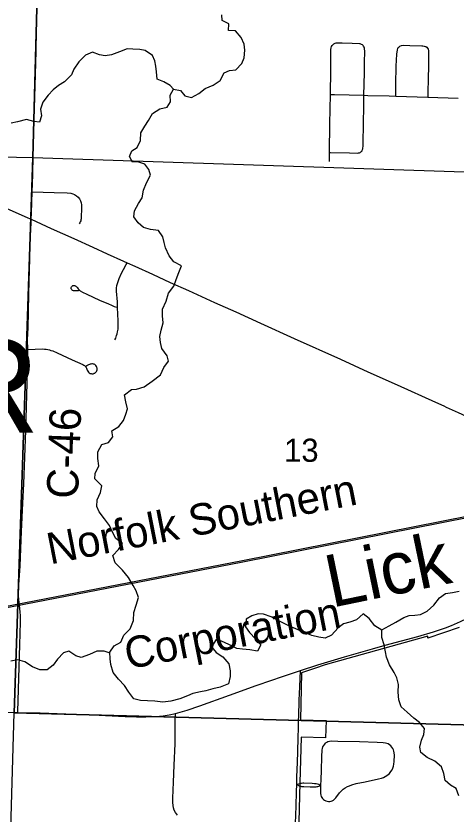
# Model space of a CAD drawing. Extents: x 0 to 34, y 0 to 22.
# Drawn here: x 5.686 to 6.482, y 19.283 to 20.728 of the extents above; entities that cross this region are included whole.
import ezdxf

# ---------------------------------------------------------------- set-up
doc = ezdxf.new("R2010")
doc.units = 0
for name, color, linetype in [('GM_X_City_Street', 7, 'Continuous'), ('GM_X_County_Road', 7, 'Continuous'), ('GM_X_County_Road_Text', 7, 'Continuous'), ('GM_X_Minor_River', 7, 'Continuous'), ('GM_X_Minor_River_Text', 7, 'Continuous'), ('GM_X_Rail_Line', 7, 'Continuous'), ('GM_X_Rail_Line_Text', 7, 'Continuous'), ('GM_X_Section', 7, 'Continuous'), ('GM_X_Section_Text', 7, 'Continuous'), ('GM_X_State_Route', 7, 'Continuous'), ('GM_X_Township_Road', 7, 'Continuous'), ('GM_X_Township_Text', 7, 'Continuous'), ('GM_X_US_Route', 7, 'Continuous')]:
    doc.layers.add(name, color=color, linetype=linetype)

msp = doc.modelspace()

# ---------------------------------------------------------------- linework, layer by layer
at = {"layer": 'GM_X_City_Street'}
for points in [[(6.2371, 19.3357), (6.237, 19.3207), (6.2374, 19.3177), (6.2381, 19.3155), (6.2392, 19.3135), (6.2406, 19.3116), (6.2422, 19.3099), (6.2441, 19.3085), (6.2467, 19.3073), (6.249, 19.3065), (6.2513, 19.3062), (6.2536, 19.3063), (6.2559, 19.3067), (6.2581, 19.3075), (6.2601, 19.3087), (6.2619, 19.3101), (6.2643, 19.3128), (6.2714, 19.3216), (6.2748, 19.3253), (6.2781, 19.3282), (6.2817, 19.3309), (6.2855, 19.3332), (6.289, 19.3348), (6.2937, 19.3364), (6.3016, 19.3385), (6.3174, 19.3419), (6.3417, 19.3473), (6.3471, 19.3485), (6.3506, 19.3497), (6.3539, 19.3512), (6.357, 19.353), (6.3593, 19.3549), (6.3615, 19.357), (6.3642, 19.3603), (6.3661, 19.3633), (6.3677, 19.3666), (6.3688, 19.37), (6.3695, 19.3736), (6.3699, 19.3784), (6.3703, 19.3902), (6.3701, 19.3945), (6.3696, 19.3974), (6.3688, 19.3996), (6.3675, 19.4022), (6.3658, 19.4047), (6.3637, 19.4069), (6.3614, 19.4088), (6.3589, 19.4104), (6.3567, 19.4113), (6.3545, 19.412), (6.3503, 19.4125), (6.3392, 19.413), (6.3075, 19.4139), (6.2683, 19.415), (6.2559, 19.4152), (6.2529, 19.4149), (6.2501, 19.4142), (6.248, 19.4132), (6.2455, 19.4116), (6.2438, 19.41), (6.242, 19.4077), (6.2406, 19.4051), (6.2397, 19.4023), (6.2392, 19.3994), (6.2387, 19.387), (6.2379, 19.3628), (6.2374, 19.3453), (6.2371, 19.3357)], [(6.1938, 19.337), (6.1948, 19.3373), (6.1976, 19.3383), (6.2008, 19.3393), (6.2028, 19.3396), (6.2048, 19.3397), (6.2065, 19.3397), (6.2218, 19.3392), (6.2257, 19.3389), (6.2291, 19.3385), (6.2317, 19.3381), (6.2337, 19.3375), (6.2356, 19.3366), (6.2371, 19.3357)], [(6.1938, 19.337), (6.1981, 19.3346), (6.201, 19.3337), (6.2026, 19.3333), (6.2046, 19.3332), (6.2065, 19.3331), (6.2184, 19.3327), (6.2213, 19.3326), (6.2242, 19.3326), (6.2267, 19.3326), (6.2291, 19.3328), (6.231, 19.3331), (6.2322, 19.3334), (6.2337, 19.334), (6.2352, 19.3347), (6.2371, 19.3357)]]:
    msp.add_lwpolyline(points, dxfattribs=at)
at = {"layer": 'GM_X_County_Road'}
for points in [[(5.7158, 20.4096), (5.7167, 20.44), (5.7175, 20.476), (5.719, 20.5313), (5.7198, 20.5604), (5.7218, 20.6219), (5.7228, 20.6641), (5.7237, 20.702), (5.7249, 20.7536), (5.7265, 20.8192)], [(6.2547, 20.5859), (6.2554, 20.6296), (6.2558, 20.6668), (6.2563, 20.6703), (6.2569, 20.6726), (6.258, 20.6744), (6.259, 20.6757)], [(6.3154, 20.5843), (6.3161, 20.6251), (6.3164, 20.6438), (6.3168, 20.6642), (6.3165, 20.6684), (6.3162, 20.67), (6.3157, 20.6715), (6.3148, 20.6732), (6.314, 20.6742), (6.3125, 20.6754), (6.3112, 20.6763), (6.31, 20.6767), (6.3088, 20.6771), (6.3072, 20.6774), (6.2939, 20.6779), (6.2758, 20.6785), (6.2643, 20.6784), (6.263, 20.6781), (6.2615, 20.6775), (6.2602, 20.6767), (6.259, 20.6757)], [(6.3729, 20.5825), (6.373, 20.5869), (6.3731, 20.6046), (6.3739, 20.6369), (6.375, 20.6586), (6.3758, 20.6667), (6.3765, 20.6687), (6.3775, 20.6705), (6.3788, 20.672), (6.3805, 20.6732), (6.383, 20.6743), (6.3863, 20.6748), (6.3981, 20.6746), (6.4199, 20.6739), (6.4221, 20.6737), (6.4243, 20.6733), (6.4262, 20.6727), (6.4275, 20.6722), (6.4289, 20.6711), (6.4304, 20.6696), (6.4313, 20.6677), (6.432, 20.6651), (6.4321, 20.6623), (6.4322, 20.6594), (6.432, 20.6463), (6.4318, 20.637), (6.4315, 20.6146), (6.431, 20.5891), (6.431, 20.586), (6.4309, 20.5807)], [(6.2532, 20.4806), (6.2533, 20.4967), (6.2536, 20.5171), (6.2538, 20.5326), (6.2547, 20.5859)], [(6.2532, 20.4806), (6.2548, 20.4806), (6.2893, 20.4799), (6.3035, 20.4796), (6.3055, 20.4798), (6.3071, 20.4803), (6.3085, 20.4808), (6.3096, 20.4816), (6.3108, 20.4826), (6.3119, 20.4838), (6.3124, 20.4848), (6.3129, 20.4858), (6.3133, 20.4873), (6.3136, 20.489), (6.3138, 20.4913), (6.314, 20.4966), (6.314, 20.5046), (6.3145, 20.5251), (6.3152, 20.5723), (6.3154, 20.5843)], [(6.2547, 20.5859), (6.2562, 20.5859), (6.262, 20.5859), (6.3154, 20.5843)], [(6.3154, 20.5843), (6.3222, 20.5841), (6.3608, 20.583), (6.3729, 20.5825)], [(6.3729, 20.5825), (6.3924, 20.5819), (6.4309, 20.5807), (6.4858, 20.579)], [(6.253, 20.4645), (6.2531, 20.4706), (6.2531, 20.4743), (6.2532, 20.4806)], [(5.714, 20.3598), (5.7146, 20.3712), (5.7158, 20.4096)], [(5.7077, 20.1243), (5.7075, 20.1416), (5.7083, 20.1639), (5.7089, 20.1925), (5.7097, 20.2254), (5.711, 20.2683), (5.7114, 20.2875), (5.7121, 20.3167), (5.7136, 20.3539), (5.714, 20.3598)], [(5.6896, 19.4674), (5.6896, 19.4693), (5.6902, 19.4892), (5.6914, 19.5295), (5.6934, 19.5897), (5.6946, 19.6307), (5.6945, 19.642), (5.6939, 19.6496), (5.6927, 19.6606), (5.6921, 19.6652), (5.6914, 19.6731), (5.6909, 19.6777), (5.6919, 19.6982), (5.6938, 19.7329), (5.6967, 19.7949), (5.6991, 19.8463), (5.7008, 19.8811), (5.7041, 19.9774), (5.707, 20.0848), (5.7077, 20.1243)], [(5.7077, 20.1243), (5.7344, 20.1252), (5.738, 20.1249), (5.7413, 20.1245), (5.7438, 20.1242), (5.747, 20.1235), (5.7497, 20.1226), (5.7529, 20.1215), (5.7609, 20.118), (5.7881, 20.1055), (5.8074, 20.0968), (5.8088, 20.096), (5.8102, 20.0952), (5.8111, 20.0945), (5.8122, 20.0934), (5.8133, 20.0917), (5.8139, 20.0903), (5.8146, 20.0885), (5.8154, 20.0867), (5.8163, 20.0848), (5.8176, 20.083), (5.8188, 20.0819), (5.8208, 20.0809), (5.8222, 20.0806), (5.8236, 20.0803), (5.8246, 20.0803), (5.8258, 20.0804), (5.827, 20.0807), (5.828, 20.0811), (5.8289, 20.0816), (5.8302, 20.0826), (5.831, 20.0833), (5.8318, 20.0844), (5.8324, 20.0857), (5.8329, 20.0874), (5.8331, 20.0888), (5.833, 20.0901), (5.8328, 20.0915), (5.832, 20.0936), (5.8308, 20.0954), (5.83, 20.0961), (5.829, 20.0968), (5.8276, 20.0974), (5.8264, 20.0978), (5.8249, 20.098), (5.8236, 20.098), (5.822, 20.0979), (5.8207, 20.0976), (5.8193, 20.0972), (5.8175, 20.0966), (5.8162, 20.096), (5.8151, 20.0954), (5.8145, 20.0948), (5.813, 20.0935)], [(6.2004, 19.5433), (6.2321, 19.5533), (6.2803, 19.5679), (6.3311, 19.5823), (6.3538, 19.5889), (6.4126, 19.605), (6.4412, 19.6135), (6.4629, 19.6207), (6.4739, 19.6249), (6.4899, 19.6318), (6.5026, 19.6381), (6.5217, 19.6485), (6.5736, 19.678), (6.5748, 19.6787)], [(5.9745, 19.4655), (5.996, 19.4715), (6.0188, 19.4795), (6.0722, 19.4984), (6.1207, 19.5158), (6.149, 19.5255), (6.1666, 19.5315), (6.2004, 19.5433)], [(6.1973, 19.4533), (6.1975, 19.4598), (6.1985, 19.4896), (6.1995, 19.5135), (6.2004, 19.5433)], [(5.6605, 19.468), (5.6896, 19.4674)], [(5.6896, 19.4674), (5.7301, 19.4666), (5.7767, 19.465), (5.8146, 19.4639), (5.8482, 19.4621), (5.8835, 19.46), (5.904, 19.4592), (5.9213, 19.4593), (5.9393, 19.4602), (5.9523, 19.4614), (5.9633, 19.4631), (5.9745, 19.4655)], [(6.1963, 19.422), (6.1963, 19.4238), (6.1968, 19.437), (6.1973, 19.4533)], [(6.1938, 19.337), (6.1938, 19.3386), (6.1942, 19.3505), (6.195, 19.3771), (6.1956, 19.3963), (6.1963, 19.422)], [(6.1883, 19.1536), (6.1885, 19.1632), (6.1892, 19.189), (6.19, 19.2159), (6.1904, 19.2311), (6.191, 19.2466), (6.1916, 19.2665), (6.1926, 19.2976), (6.1935, 19.3243), (6.1938, 19.337)]]:
    msp.add_lwpolyline(points, dxfattribs=at)
at = {"layer": 'GM_X_Minor_River'}
for points in [[(5.895, 20.0519), (5.9045, 20.0521), (5.9183, 20.0567), (5.9325, 20.0667), (5.9479, 20.0782), (5.9538, 20.0914), (5.962, 20.1033), (5.9599, 20.1129), (5.9503, 20.126), (5.9475, 20.1366), (5.9466, 20.1477), (5.9491, 20.159), (5.9527, 20.1722), (5.9511, 20.1848), (5.9513, 20.1973), (5.9577, 20.2116), (5.9621, 20.2263), (5.9718, 20.239), (5.9759, 20.2507), (5.9807, 20.2635), (5.9858, 20.2756), (5.9719, 20.2827), (5.9634, 20.2938), (5.9569, 20.308), (5.9544, 20.3175), (5.9519, 20.3278), (5.9438, 20.3398), (5.9298, 20.3412), (5.917, 20.3448), (5.9073, 20.3534), (5.8996, 20.3645), (5.9005, 20.3751), (5.908, 20.3883), (5.9146, 20.3988), (5.9172, 20.4124), (5.9224, 20.4256), (5.9294, 20.4395), (5.9266, 20.4502), (5.9196, 20.4598), (5.9068, 20.4638), (5.8973, 20.4629), (5.8914, 20.4736), (5.8958, 20.4838), (5.9054, 20.49), (5.9117, 20.5024), (5.9123, 20.5161), (5.9194, 20.5285), (5.926, 20.5386), (5.9331, 20.551), (5.9466, 20.5598), (5.9599, 20.5626), (5.9658, 20.5724), (5.9652, 20.5845), (5.9711, 20.5954), (5.9836, 20.5929), (5.9914, 20.5833), (6.0038, 20.5804), (6.0169, 20.5873), (6.0284, 20.5966), (6.0429, 20.6028), (6.0552, 20.6109), (6.0627, 20.6248), (6.0726, 20.6288), (6.084, 20.6301), (6.0949, 20.6416), (6.0989, 20.6518), (6.1003, 20.6658), (6.099, 20.6768), (6.0935, 20.6887), (6.0835, 20.701), (6.0703, 20.7013), (6.0709, 20.7134), (6.0592, 20.7197), (6.0583, 20.7296)], [(5.9711, 20.5954), (5.9652, 20.602), (5.9536, 20.6083), (5.9419, 20.6134), (5.9406, 20.6268), (5.9393, 20.6367), (5.9372, 20.6466), (5.9329, 20.6565), (5.9201, 20.6651), (5.9103, 20.6668), (5.8978, 20.6678), (5.8876, 20.6684), (5.8738, 20.663), (5.8589, 20.6576), (5.8475, 20.6555), (5.8373, 20.6572), (5.8245, 20.6624), (5.8119, 20.6566), (5.7999, 20.645), (5.7909, 20.6312), (5.7866, 20.621), (5.7742, 20.6087), (5.7635, 20.6021), (5.7534, 20.5943), (5.7449, 20.5846), (5.7352, 20.5715), (5.7308, 20.5591), (5.7328, 20.5473), (5.7288, 20.5356), (5.719, 20.5369), (5.7054, 20.5406), (5.6894, 20.5364), (5.6776, 20.5335)], [(6.3474, 19.6161), (6.335, 19.624), (6.3247, 19.6375), (6.3138, 19.646), (6.3019, 19.6349), (6.2896, 19.6306), (6.2786, 19.6277), (6.269, 19.6203), (6.2569, 19.6069), (6.2451, 19.6018), (6.2341, 19.6035), (6.2209, 19.6065), (6.2062, 19.6124), (6.1923, 19.6184), (6.1822, 19.6231), (6.169, 19.6295), (6.1593, 19.6342), (6.1476, 19.6401), (6.1341, 19.6453), (6.1242, 19.6459), (6.1128, 19.6423), (6.1024, 19.6361), (6.101, 19.6221), (6.1084, 19.6121), (6.1192, 19.6005), (6.1288, 19.5896), (6.1229, 19.5784), (6.1093, 19.5805), (6.0961, 19.5819), (6.0858, 19.5833), (6.0712, 19.59), (6.058, 19.5963), (6.0482, 19.5996), (6.04, 19.586), (6.0482, 19.5756), (6.0605, 19.5678), (6.0713, 19.5551), (6.0733, 19.5425), (6.0735, 19.5326), (6.0706, 19.5194), (6.0557, 19.5129), (6.0423, 19.5101), (6.0298, 19.5065), (6.0199, 19.5045), (6.0058, 19.5017), (5.9962, 19.4973), (5.9825, 19.4919), (5.9665, 19.4877), (5.9516, 19.4857), (5.9376, 19.4878), (5.924, 19.4885), (5.9115, 19.4891), (5.8994, 19.492), (5.8902, 19.5039), (5.8824, 19.5162), (5.8717, 19.5278), (5.8624, 19.5398), (5.8581, 19.5539), (5.8568, 19.5642), (5.8563, 19.5763), (5.8641, 19.5879), (5.876, 19.5945), (5.8815, 19.6073), (5.8928, 19.6189), (5.8987, 19.6339), (5.8994, 19.6484), (5.9038, 19.6615), (5.9079, 19.6755), (5.9039, 19.6877), (5.8981, 19.6973), (5.8896, 19.7115), (5.8789, 19.7247), (5.8655, 19.7382), (5.8616, 19.7512), (5.8716, 19.762), (5.8787, 19.7732), (5.8671, 19.7822), (5.8601, 19.7945), (5.8554, 19.8059), (5.8465, 19.8175), (5.8365, 19.8302), (5.8326, 19.8398), (5.8332, 19.8519), (5.8395, 19.8651), (5.8416, 19.8772), (5.829, 19.89), (5.8295, 19.8998), (5.8359, 19.9137), (5.8342, 19.9267), (5.8341, 19.9392), (5.8419, 19.952), (5.8534, 19.9559), (5.8615, 19.966), (5.8595, 19.9767), (5.8721, 19.9851), (5.8807, 19.9956), (5.8847, 20.0069), (5.8883, 20.0167), (5.8848, 20.0297), (5.8823, 20.0423), (5.895, 20.0519)], [(6.4868, 19.3167), (6.4818, 19.3297), (6.472, 19.3355), (6.4623, 19.3441), (6.4599, 19.357), (6.4556, 19.3689), (6.4433, 19.3794), (6.4298, 19.3857), (6.4182, 19.3947), (6.4161, 19.4042), (6.4194, 19.4174), (6.4234, 19.4276), (6.4251, 19.4382), (6.4158, 19.449), (6.4057, 19.4568), (6.3934, 19.468), (6.3826, 19.4773), (6.3783, 19.4903), (6.3771, 19.504), (6.3777, 19.5176), (6.3749, 19.5298), (6.3702, 19.5398), (6.3617, 19.5536), (6.3563, 19.5674), (6.3546, 19.5769), (6.3518, 19.5899), (6.3479, 19.6029), (6.3474, 19.6169), (6.3608, 19.6239), (6.3731, 19.6305), (6.3873, 19.6393), (6.3972, 19.6425), (6.4071, 19.6431), (6.4173, 19.6448), (6.4296, 19.6506), (6.4415, 19.6614), (6.452, 19.6745), (6.4628, 19.6826), (6.4757, 19.6846), (6.4872, 19.6871)], [(5.8564, 19.5745), (5.8457, 19.578), (5.8324, 19.5783), (5.8194, 19.5721), (5.8045, 19.5667), (5.7944, 19.5695), (5.782, 19.5781), (5.7725, 19.5753), (5.7612, 19.5637), (5.7535, 19.5529), (5.7431, 19.5447), (5.7294, 19.5442), (5.7162, 19.5498), (5.7024, 19.5588), (5.6899, 19.5628), (5.677, 19.5604)]]:
    msp.add_lwpolyline(points, dxfattribs=at)
at = {"layer": 'GM_X_Rail_Line'}
for points in [[(2.1, 18.9599), (2.5738, 19.0523), (3.1234, 19.1602), (3.6767, 19.2666), (4.2609, 19.3838), (4.9006, 19.5087), (5.4948, 19.6259), (6.096, 19.7423), (6.7148, 19.8649), (7.2736, 19.9767), (7.8416, 20.0877), (8.2886, 20.1741), (8.3633, 20.1886), (8.9, 20.2933)], [(2.1, 18.9575), (2.5743, 19.05), (3.1238, 19.158), (3.6772, 19.2644), (4.2614, 19.3816), (4.9011, 19.5065), (5.4953, 19.6236), (6.0964, 19.7401), (6.7153, 19.8626), (7.2741, 19.9744), (7.8421, 20.0855), (8.2891, 20.1718), (8.3637, 20.1864), (8.9, 20.2909)]]:
    msp.add_lwpolyline(points, dxfattribs=at)
at = {"layer": 'GM_X_Rail_Line_Text'}
for points in [[(5.7281, 20.9), (4.6953, 20.9), (4.6829, 20.4926), (5.7169, 20.4716)], [(6.7246, 20.9), (5.7281, 20.9), (5.7169, 20.4716), (6.7143, 20.4382), (6.7151, 20.4719)]]:
    msp.add_lwpolyline(points, close=True, dxfattribs=at)
at = {"layer": 'GM_X_Section'}
for points in [[(4.6829, 20.4926), (5.7169, 20.4716), (5.6833, 19.4667), (4.6614, 19.4847)], [(5.7169, 20.4716), (6.7143, 20.4382), (6.6979, 19.4726), (6.6975, 19.4397), (5.6833, 19.4667)], [(5.6833, 19.4667), (6.6975, 19.4397), (6.6853, 18.443), (5.6535, 18.4609)]]:
    msp.add_lwpolyline(points, close=True, dxfattribs=at)
at = {"layer": 'GM_X_State_Route'}
for points in [[(5.669, 20.3798), (5.7077, 20.3626), (5.714, 20.3598)], [(5.714, 20.3598), (5.7502, 20.3434), (5.791, 20.325), (5.8255, 20.3093), (5.8515, 20.2974), (5.8809, 20.284), (5.8872, 20.2811), (5.9013, 20.2748), (5.9329, 20.2603), (5.9652, 20.2455), (5.998, 20.2307), (6.045, 20.2094), (6.0836, 20.1921), (6.1283, 20.1718), (6.1895, 20.1441), (6.2728, 20.1065), (6.3226, 20.0839), (6.3753, 20.0601), (6.4444, 20.0289), (6.4595, 20.0221)], [(6.4595, 20.0221), (6.4642, 20.0199), (6.4857, 20.0101), (6.5214, 19.9938), (6.5329, 19.9891), (6.5394, 19.9867), (6.5476, 19.9838), (6.5543, 19.9817), (6.5601, 19.9801), (6.5673, 19.9781), (6.5741, 19.9766), (6.5888, 19.9738), (6.6032, 19.9718), (6.6148, 19.9708), (6.6316, 19.9699), (6.6633, 19.9696), (6.6968, 19.9692), (6.7158, 19.9684)]]:
    msp.add_lwpolyline(points, dxfattribs=at)
at = {"layer": 'GM_X_Township_Road'}
for points in [[(5.7158, 20.4096), (5.7554, 20.4085), (5.779, 20.4076), (5.7853, 20.4068), (5.7891, 20.4059), (5.792, 20.4047), (5.7958, 20.4022), (5.7987, 20.3996), (5.8011, 20.3966), (5.8029, 20.3931), (5.8042, 20.3895), (5.8049, 20.3857), (5.805, 20.38), (5.8045, 20.3632), (5.8042, 20.3609), (5.8039, 20.3588), (5.8034, 20.3568), (5.8027, 20.3551), (5.8019, 20.3535), (5.8008, 20.3516)], [(5.8701, 20.2004), (5.8697, 20.2104), (5.8683, 20.2295), (5.8682, 20.2351), (5.8689, 20.24), (5.8704, 20.2454), (5.8729, 20.2524), (5.8772, 20.262), (5.8806, 20.2688), (5.8855, 20.2778), (5.8872, 20.2811)], [(5.8006, 20.2309), (5.7988, 20.2306), (5.7964, 20.2303), (5.7941, 20.2301), (5.7926, 20.2301), (5.7913, 20.2302), (5.7902, 20.2304), (5.7893, 20.2307), (5.7885, 20.2311), (5.7877, 20.2317), (5.7872, 20.2323), (5.7867, 20.2331), (5.7863, 20.234), (5.7861, 20.235), (5.7864, 20.2364), (5.7867, 20.2375), (5.7872, 20.2383), (5.7879, 20.2389), (5.7887, 20.2394), (5.7895, 20.2397), (5.7904, 20.24), (5.7914, 20.24), (5.7923, 20.2398), (5.7932, 20.2396), (5.7941, 20.2392), (5.7948, 20.2387), (5.7955, 20.2382), (5.7961, 20.2374), (5.7968, 20.2367), (5.7974, 20.2358), (5.7988, 20.2339), (5.8004, 20.2321), (5.8023, 20.2305), (5.8066, 20.2281), (5.8144, 20.2243), (5.8376, 20.2137), (5.8534, 20.2065), (5.859, 20.2042), (5.8642, 20.2022), (5.8687, 20.2008), (5.8701, 20.2004)], [(5.8654, 20.1419), (5.8667, 20.1447), (5.8676, 20.1469), (5.8684, 20.1493), (5.8692, 20.1523), (5.8701, 20.1559), (5.8707, 20.1586), (5.871, 20.1609), (5.8711, 20.1635), (5.8712, 20.1657), (5.8712, 20.1705), (5.8712, 20.1763), (5.8701, 20.2004)], [(5.9781, 19.2815), (5.9748, 19.286), (5.9725, 19.2904), (5.9711, 19.2945), (5.9703, 19.2988), (5.9699, 19.3044), (5.97, 19.3124), (5.971, 19.341), (5.9725, 19.372), (5.9739, 19.4105), (5.9744, 19.4328), (5.9743, 19.4515), (5.9745, 19.4655)]]:
    msp.add_lwpolyline(points, dxfattribs=at)
at = {"layer": 'GM_X_US_Route'}
msp.add_lwpolyline([(6.4874, 19.6208), (6.431, 19.6015), (6.4311, 19.6055), (6.2453, 19.5532), (6.2257, 19.5471), (6.2026, 19.5391), (6.2006, 19.4539), (6.2468, 19.4526), (6.246, 19.4212), (6.2016, 19.4225), (6.1996, 19.3397), (6.1974, 19.2691)], dxfattribs=at)

# ---------------------------------------------------------------- texts
at = {"layer": 'GM_X_County_Road_Text'}
msp.add_text('C-46', height=0.05682, rotation=87.944, dxfattribs=at).set_placement((5.7985, 19.8533))
at = {"layer": 'GM_X_Minor_River_Text'}
msp.add_text('Lick', height=0.09476, rotation=11.671, dxfattribs=at).set_placement((6.2569, 19.6567))
at = {"layer": 'GM_X_Rail_Line_Text'}
for s, rotation, p in [('Norfolk Southern', 11.0655, (5.7483, 19.7351)), ('Corporation', 11.1636, (5.8888, 19.5451))]:
    msp.add_text(s, height=0.056629, rotation=rotation, dxfattribs=at).set_placement(p)
at = {"layer": 'GM_X_Section_Text'}
msp.add_text('13', height=0.04186, rotation=0, dxfattribs=at).set_placement((6.1711, 19.9209))
at = {"layer": 'GM_X_Township_Text'}
msp.add_text('CENTER', height=0.17045, rotation=0, dxfattribs=at).set_placement((4.7913, 19.9736))

doc.saveas('drawing.dxf')
